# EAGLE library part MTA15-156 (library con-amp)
AMP connector
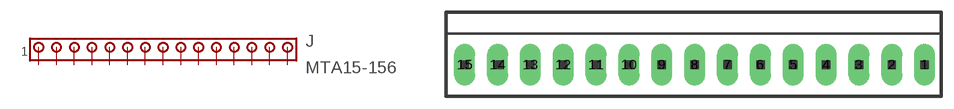
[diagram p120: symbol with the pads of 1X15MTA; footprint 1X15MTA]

Designator prefix J

## MTA15-156 (OC_FARNELL: unknown; OC_NEWARK: unknown)  [1X15MTA]
1  1  pas
2  2  pas
3  3  pas
4  4  pas
5  5  pas
6  6  pas
7  7  pas
8  8  pas
9  9  pas
10  10  pas
11  11  pas
12  12  pas
13  13  pas
14  14  pas
15  15  pas

## Footprint 1X15MTA (pad centres in mm)
AMP MTA connector
drill 1.676 long: 1 27.737,0; 2 23.774,0; 3 19.812,0; 4 15.85,0; 5 11.887,0; 6 7.925,0; 7 3.962,0; 8 0,0; 9 -3.962,0; 10 -7.925,0; 11 -11.887,0; 12 -15.85,0; 13 -19.812,0; 14 -23.774,0; 15 -27.737,0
